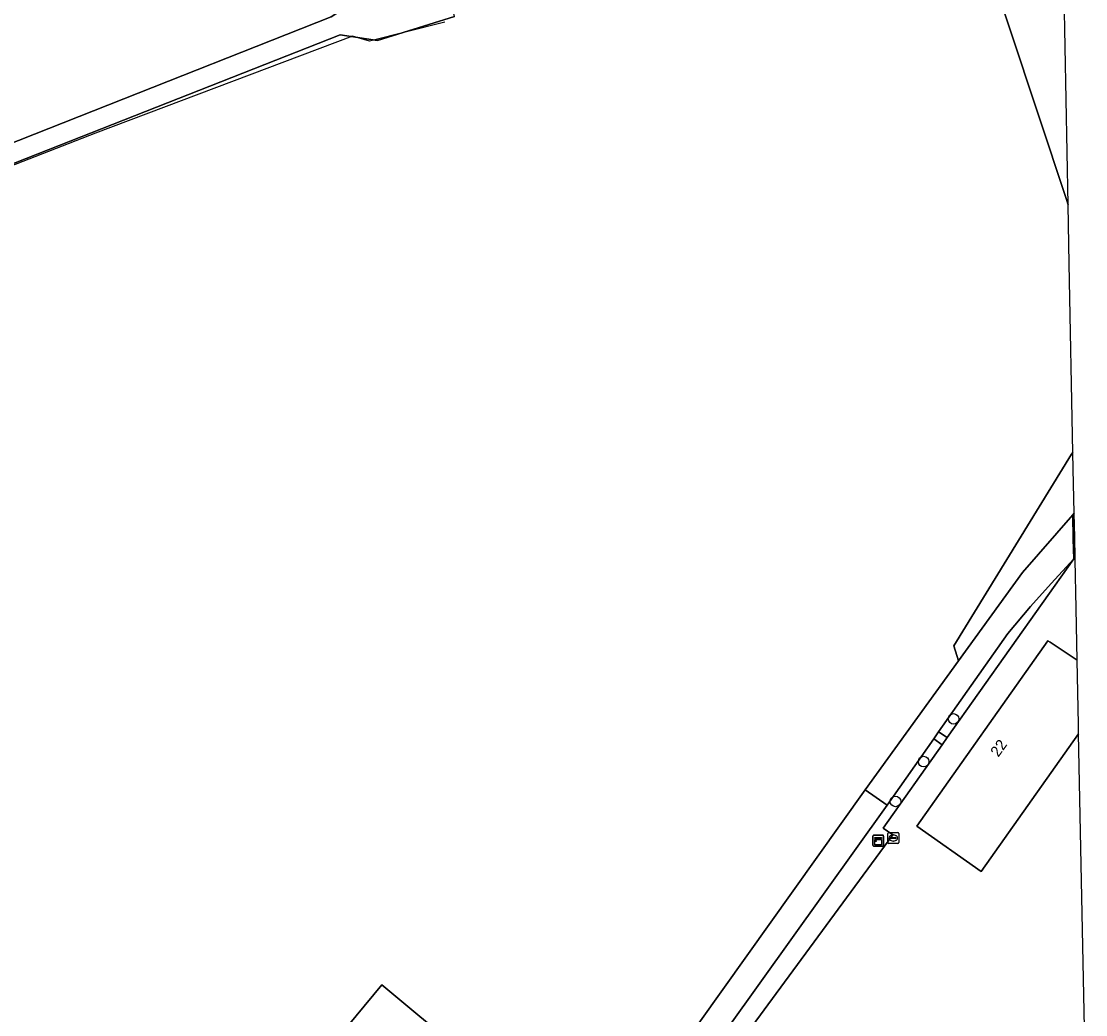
# Model space of a CAD drawing. Extents: x 163859 to 164644, y 379566 to 382155.
# Drawn here: x 164505.3 to 164603.3, y 381680.8 to 381772.4 of the extents above; entities that cross this region are included whole.
import ezdxf

# ---------------------------------------------------------------- set-up
doc = ezdxf.new("R2010")
doc.units = 0
for name, color, linetype in [('IMGEO_Berm_groen', 7, 'Continuous'), ('IMGEO_Boom', 7, 'Continuous'), ('IMGEO_Erf', 7, 'Continuous'), ('IMGEO_Grasland_agrarisch', 7, 'Continuous'), ('IMGEO_Groenvoorziening', 7, 'Continuous'), ('IMGEO_Hek', 7, 'Continuous'), ('IMGEO_Kast', 7, 'Continuous'), ('IMGEO_Pand', 7, 'Continuous'), ('IMGEO_Pand_nummerreeks', 7, 'Continuous'), ('IMGEO_Rijbaan_lokaal_halfverhard', 7, 'Continuous'), ('IMGEO_Rijbaan_lokaal_onverhard', 7, 'Continuous'), ('IMGEO_Rioolput', 7, 'Continuous'), ('IMGEO_Voetpad_open', 7, 'Continuous')]:
    doc.layers.add(name, color=color, linetype=linetype)

msp = doc.modelspace()

# ---------------------------------------------------------------- linework, layer by layer
at = {"layer": 'IMGEO_Berm_groen'}
msp.add_lwpolyline([(164602.163, 381732.626), (164602.042, 381732.452), (164591.186, 381714.808), (164591.612, 381713.421), (164597.502, 381721.573), (164602.15, 381726.888), (164602.274, 381727.03), (164602.193, 381731.101)], close=True, dxfattribs=at)
at = {"layer": 'IMGEO_Boom'}
for centre in [(164591.162, 381708.074), (164588.407, 381704.135), (164585.816, 381700.469)]:
    msp.add_circle(centre, 0.489, dxfattribs=at)
at = {"layer": 'IMGEO_Erf'}
for points in [[(164600.098, 381839.014), (164585.232, 381833.12), (164548.829, 381818.751), (164518.638, 381806.884), (164490.643, 381796.474), (164469.448, 381788.316), (164427.546, 381772.442), (164433.526, 381754.803), (164433.997, 381752.734), (164434.331, 381751.745), (164440.833, 381734.263), (164457.1, 381740.602), (164468.83, 381745.172), (164534.647, 381771.115), (164538.087, 381770.586), (164545.187, 381772.796), (164541.615, 381789.068), (164575.754, 381802.969), (164581.346, 381805.246), (164580.013, 381810.414), (164568.257, 381805.885), (164561.666, 381820.235), (164600.165, 381835.553), (164600.153, 381836.164)], [(164443.539, 381737.474), (164442.939, 381737.247), (164436.966, 381753.014), (164430.965, 381770.512), (164456.78, 381779.759), (164478.348, 381787.868), (164505.546, 381798.321), (164526.662, 381806.514), (164530.385, 381805.09), (164531.541, 381804.475), (164532.487, 381803.404), (164538.297, 381784.937), (164539.439, 381780.675), (164539.19, 381777.888), (164537.822, 381775.597), (164535.89, 381774.091), (164533.834, 381772.761), (164490.018, 381755.433)], [(164545.843, 381677.45), (164529.89, 381658.17), (164522.527, 381664.272), (164538.507, 381683.582)]]:
    msp.add_lwpolyline(points, close=True, dxfattribs=at)
for points in [[(164565.496, 381676.942), (164583.03, 381701.542), (164591.612, 381713.421), (164591.186, 381714.808), (164602.042, 381732.452), (164602.163, 381732.626), (164601.827, 381750), (164601.721, 381755.446), (164601.588, 381755.851), (164583.079, 381811.658)], [(164545.187, 381772.796), (164538.087, 381770.586), (164534.647, 381771.115), (164468.83, 381745.172), (164457.1, 381740.602), (164440.833, 381734.263), (164442.117, 381733.052), (164446.861, 381722.173), (164449.308, 381717.487), (164452.858, 381710.476), (164454.684, 381705.828), (164452.839, 381705.104), (164456.242, 381696.233), (164460.508, 381684.892), (164470.413, 381677.426)], [(164603.336, 381673.583), (164602.678, 381706.699), (164593.719, 381694.013), (164587.786, 381698.2), (164599.842, 381715.281), (164600.069, 381715.129), (164602.543, 381713.471), (164602.448, 381718.255), (164602.36, 381722.725), (164602.355, 381722.96), (164602.228, 381722.832), (164590.579, 381706.347), (164590.112, 381705.686), (164584.68, 381697.999), (164585.565, 381697.385), (164584.369, 381695.756), (164568.781, 381674.53)]]:
    msp.add_lwpolyline(points, dxfattribs=at)
at = {"layer": 'IMGEO_Grasland_agrarisch'}
for points in [[(164601.721, 381755.446), (164601.248, 381779.746), (164600.491, 381818.66), (164598.446, 381817.895), (164593.065, 381815.711), (164583.079, 381811.658), (164601.588, 381755.851)], [(164443.539, 381737.474), (164490.018, 381755.433), (164533.834, 381772.761), (164535.89, 381774.091), (164537.822, 381775.597), (164539.19, 381777.888), (164539.439, 381780.675), (164538.297, 381784.937), (164532.487, 381803.404), (164531.541, 381804.475), (164530.385, 381805.09), (164526.662, 381806.514), (164505.546, 381798.321), (164478.348, 381787.868), (164456.78, 381779.759), (164430.965, 381770.512), (164436.966, 381753.014), (164442.939, 381737.247)]]:
    msp.add_lwpolyline(points, close=True, dxfattribs=at)
at = {"layer": 'IMGEO_Groenvoorziening'}
for points in [[(164602.228, 381722.832), (164600.169, 381720.56), (164598.261, 381718.444), (164596.17, 381715.955), (164589.789, 381706.869), (164590.579, 381706.347)], [(164590.112, 381705.686), (164589.347, 381706.241), (164585.059, 381700.136), (164567.438, 381675.517), (164539.232, 381640.645), (164531.152, 381631.205), (164529.998, 381629.477), (164530.675, 381628.727), (164531.061, 381628.3), (164531.447, 381627.873), (164531.903, 381627.368), (164540.995, 381639.172), (164569.412, 381674.265), (164568.781, 381674.53), (164584.369, 381695.756), (164585.565, 381697.385), (164584.68, 381697.999)]]:
    msp.add_lwpolyline(points, close=True, dxfattribs=at)
at = {"layer": 'IMGEO_Hek'}
for points in [[(164544.296, 381772.277), (164537.363, 381770.508), (164535.776, 381770.974), (164512.128, 381762.042)], [(164512.128, 381762.042), (164479.577, 381749.36)]]:
    msp.add_lwpolyline(points, dxfattribs=at)
at = {"layer": 'IMGEO_Kast'}
for p, q in [((164583.723, 381696.427), (164583.723, 381697.268)), ((164583.723, 381697.268), (164583.723, 381696.427)), ((164583.798, 381697.352), (164584.639, 381697.352)), ((164584.639, 381697.352), (164583.798, 381697.352)), ((164584.723, 381697.277), (164584.723, 381696.436)), ((164584.723, 381696.436), (164584.723, 381697.277)), ((164584.648, 381696.352), (164583.807, 381696.352)), ((164583.807, 381696.352), (164584.648, 381696.352))]:
    msp.add_line(p, q, dxfattribs=at)
for points in [[(164583.918, 381697.142), (164584.518, 381697.142), (164584.518, 381697.057), (164583.918, 381697.057), (164583.918, 381697.142)], [(164583.918, 381696.967), (164584.518, 381696.967), (164584.518, 381696.478), (164583.918, 381696.478), (164583.918, 381696.967)]]:
    msp.add_lwpolyline(points, dxfattribs=at)
msp.add_circle((164584.002, 381696.816), 0.0377, dxfattribs=at)
for centre, start, end in [((164583.801, 381697.274), 92.4484, 184.28452), ((164583.801, 381697.274), 92.4484, 184.28452), ((164584.645, 381697.274), 2.4484, 94.28452), ((164584.645, 381697.274), 2.4484, 94.28452), ((164583.801, 381696.43), 182.4484, 274.28452), ((164583.801, 381696.43), 182.4484, 274.28452), ((164584.645, 381696.43), 272.4484, 4.28452), ((164584.645, 381696.43), 272.4484, 4.28452)]:
    msp.add_arc(centre, 0.0779, start, end, dxfattribs=at)
at = {"layer": 'IMGEO_Pand'}
for points in [[(164602.678, 381706.699), (164602.661, 381707.545), (164602.543, 381713.471), (164600.069, 381715.129), (164599.842, 381715.281), (164587.786, 381698.2), (164593.719, 381694.013)], [(164545.843, 381677.45), (164538.507, 381683.582), (164522.527, 381664.272), (164529.89, 381658.17)]]:
    msp.add_lwpolyline(points, close=True, dxfattribs=at)
at = {"layer": 'IMGEO_Rijbaan_lokaal_halfverhard'}
for points in [[(164596.17, 381715.955), (164598.261, 381718.444), (164600.169, 381720.56), (164602.228, 381722.832), (164602.193, 381724.649), (164602.15, 381726.888), (164597.502, 381721.573), (164591.612, 381713.421), (164583.03, 381701.542), (164585.059, 381700.136), (164589.347, 381706.241), (164589.789, 381706.869)], [(164567.438, 381675.517), (164585.059, 381700.136), (164583.03, 381701.542), (164565.496, 381676.942), (164553.793, 381662.786), (164545.262, 381652.467), (164545.675, 381652.106), (164539.821, 381645.024), (164529.996, 381633.747), (164524.226, 381630.763), (164528.858, 381625.543), (164529.062, 381628.074), (164529.998, 381629.477), (164531.152, 381631.205), (164539.232, 381640.645)]]:
    msp.add_lwpolyline(points, close=True, dxfattribs=at)
at = {"layer": 'IMGEO_Rijbaan_lokaal_onverhard'}
msp.add_lwpolyline([(164602.274, 381727.03), (164602.15, 381726.888), (164602.193, 381724.649), (164602.228, 381722.832), (164602.355, 381722.96), (164602.319, 381724.781)], close=True, dxfattribs=at)
at = {"layer": 'IMGEO_Rioolput'}
for p, q in [((164585.109, 381696.674), (164585.109, 381697.526)), ((164585.184, 381697.6), (164586.036, 381697.6)), ((164585.368, 381697.094), (164585.368, 381697.106)), ((164585.806, 381697.057), (164585.408, 381697.057)), ((164585.411, 381697.143), (164585.809, 381697.143)), ((164585.597, 381697.38), (164585.622, 381697.38)), ((164585.852, 381697.106), (164585.852, 381697.094)), ((164586.11, 381697.526), (164586.11, 381696.674)), ((164586.036, 381696.6), (164585.184, 381696.6)), ((164585.62, 381696.82), (164585.595, 381696.82))]:
    msp.add_line(p, q, dxfattribs=at)
for points in [[(164585.109, 381696.674), (164585.109, 381697.526)], [(164585.184, 381697.6), (164586.036, 381697.6)], [(164586.11, 381697.526), (164586.11, 381696.674)], [(164586.036, 381696.6), (164585.184, 381696.6)]]:
    msp.add_lwpolyline(points, dxfattribs=at)
for centre, radius, start, end in [((164585.186, 381697.524), 0.0765, 91.55205, 178.44795), ((164585.186, 381697.524), 0.0765, 91.55205, 178.44795), ((164585.408, 381697.103), 0.0403, 85.87752, 175.75265), ((164585.405, 381697.093), 0.0366, 178.93798, 274.71019), ((164585.809, 381697.1), 0.043, 264.86636, 352.45326), ((164585.813, 381697.105), 0.0386, 1.73085, 96.63898), ((164586.034, 381697.524), 0.0765, 1.55205, 88.44795), ((164586.034, 381697.524), 0.0765, 1.55205, 88.44795), ((164585.186, 381696.676), 0.0765, 181.55205, 268.44795), ((164585.186, 381696.676), 0.0765, 181.55205, 268.44795), ((164586.034, 381696.676), 0.0765, 271.55205, 358.44795), ((164586.034, 381696.676), 0.0765, 271.55205, 358.44795)]:
    msp.add_arc(centre, radius, start, end, dxfattribs=at)
for centre, major_axis, ratio, start_param, end_param in [((164585.596, 381697.1), (-0.387, 0.002), 0.722429, 4.712389, 7.853982), ((164585.621, 381697.1), (-0.39, 0.002), 0.717154, 1.570796, 4.712389)]:
    msp.add_ellipse(centre, major_axis=major_axis, ratio=ratio, start_param=start_param, end_param=end_param, dxfattribs=at)
at = {"layer": 'IMGEO_Voetpad_open'}
msp.add_lwpolyline([(164590.579, 381706.347), (164589.789, 381706.869), (164589.347, 381706.241), (164590.112, 381705.686)], close=True, dxfattribs=at)

# ---------------------------------------------------------------- texts
at = {"layer": 'IMGEO_Pand_nummerreeks'}
msp.add_text('22', height=1, rotation=54.58569, dxfattribs=at).set_placement((164595.291, 381704.502))

doc.saveas('drawing.dxf')
